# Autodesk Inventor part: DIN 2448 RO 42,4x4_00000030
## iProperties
Created: 2006-02
Part Number: DIN 2448 RO 42,4x4_00000030
Material: Default
Document SubType Name: Modeling
Designer: FranzK
Stock Number: DIN 2448 RO 42,4x4
Mass: 421.966 g
Surface Area: 2123.47 cm^2
Volume: 421.966 cm^3
Density: 1 g/cm^3
G_L: 890.000 mm
G_W: 42.400 mm
G_H: 42.400 mm
AFG_Item: 42.4 x 4
CSToolsMass: 0.4
CSToolsVolume: 421966.0
CSToolsArea: 2123.0
Author: FranzK
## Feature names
1. AFG_Detailed_DIN 2448 RO 42,4x4_00000030 [Extrusion]
2. AFG_Simplified_DIN 2448 RO 42,4x4_00000030 [Extrusion]
3. AFG_StartExtrusion_1 [Extrusion]
4. AFG_StartExtrusion_2 [Extrusion]
